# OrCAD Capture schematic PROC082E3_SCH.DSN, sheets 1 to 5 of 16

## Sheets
1 01. TABLE OF CONTENTS: title: TABLE OF CONTENTS; rev: E3; note: PROC082_SCH
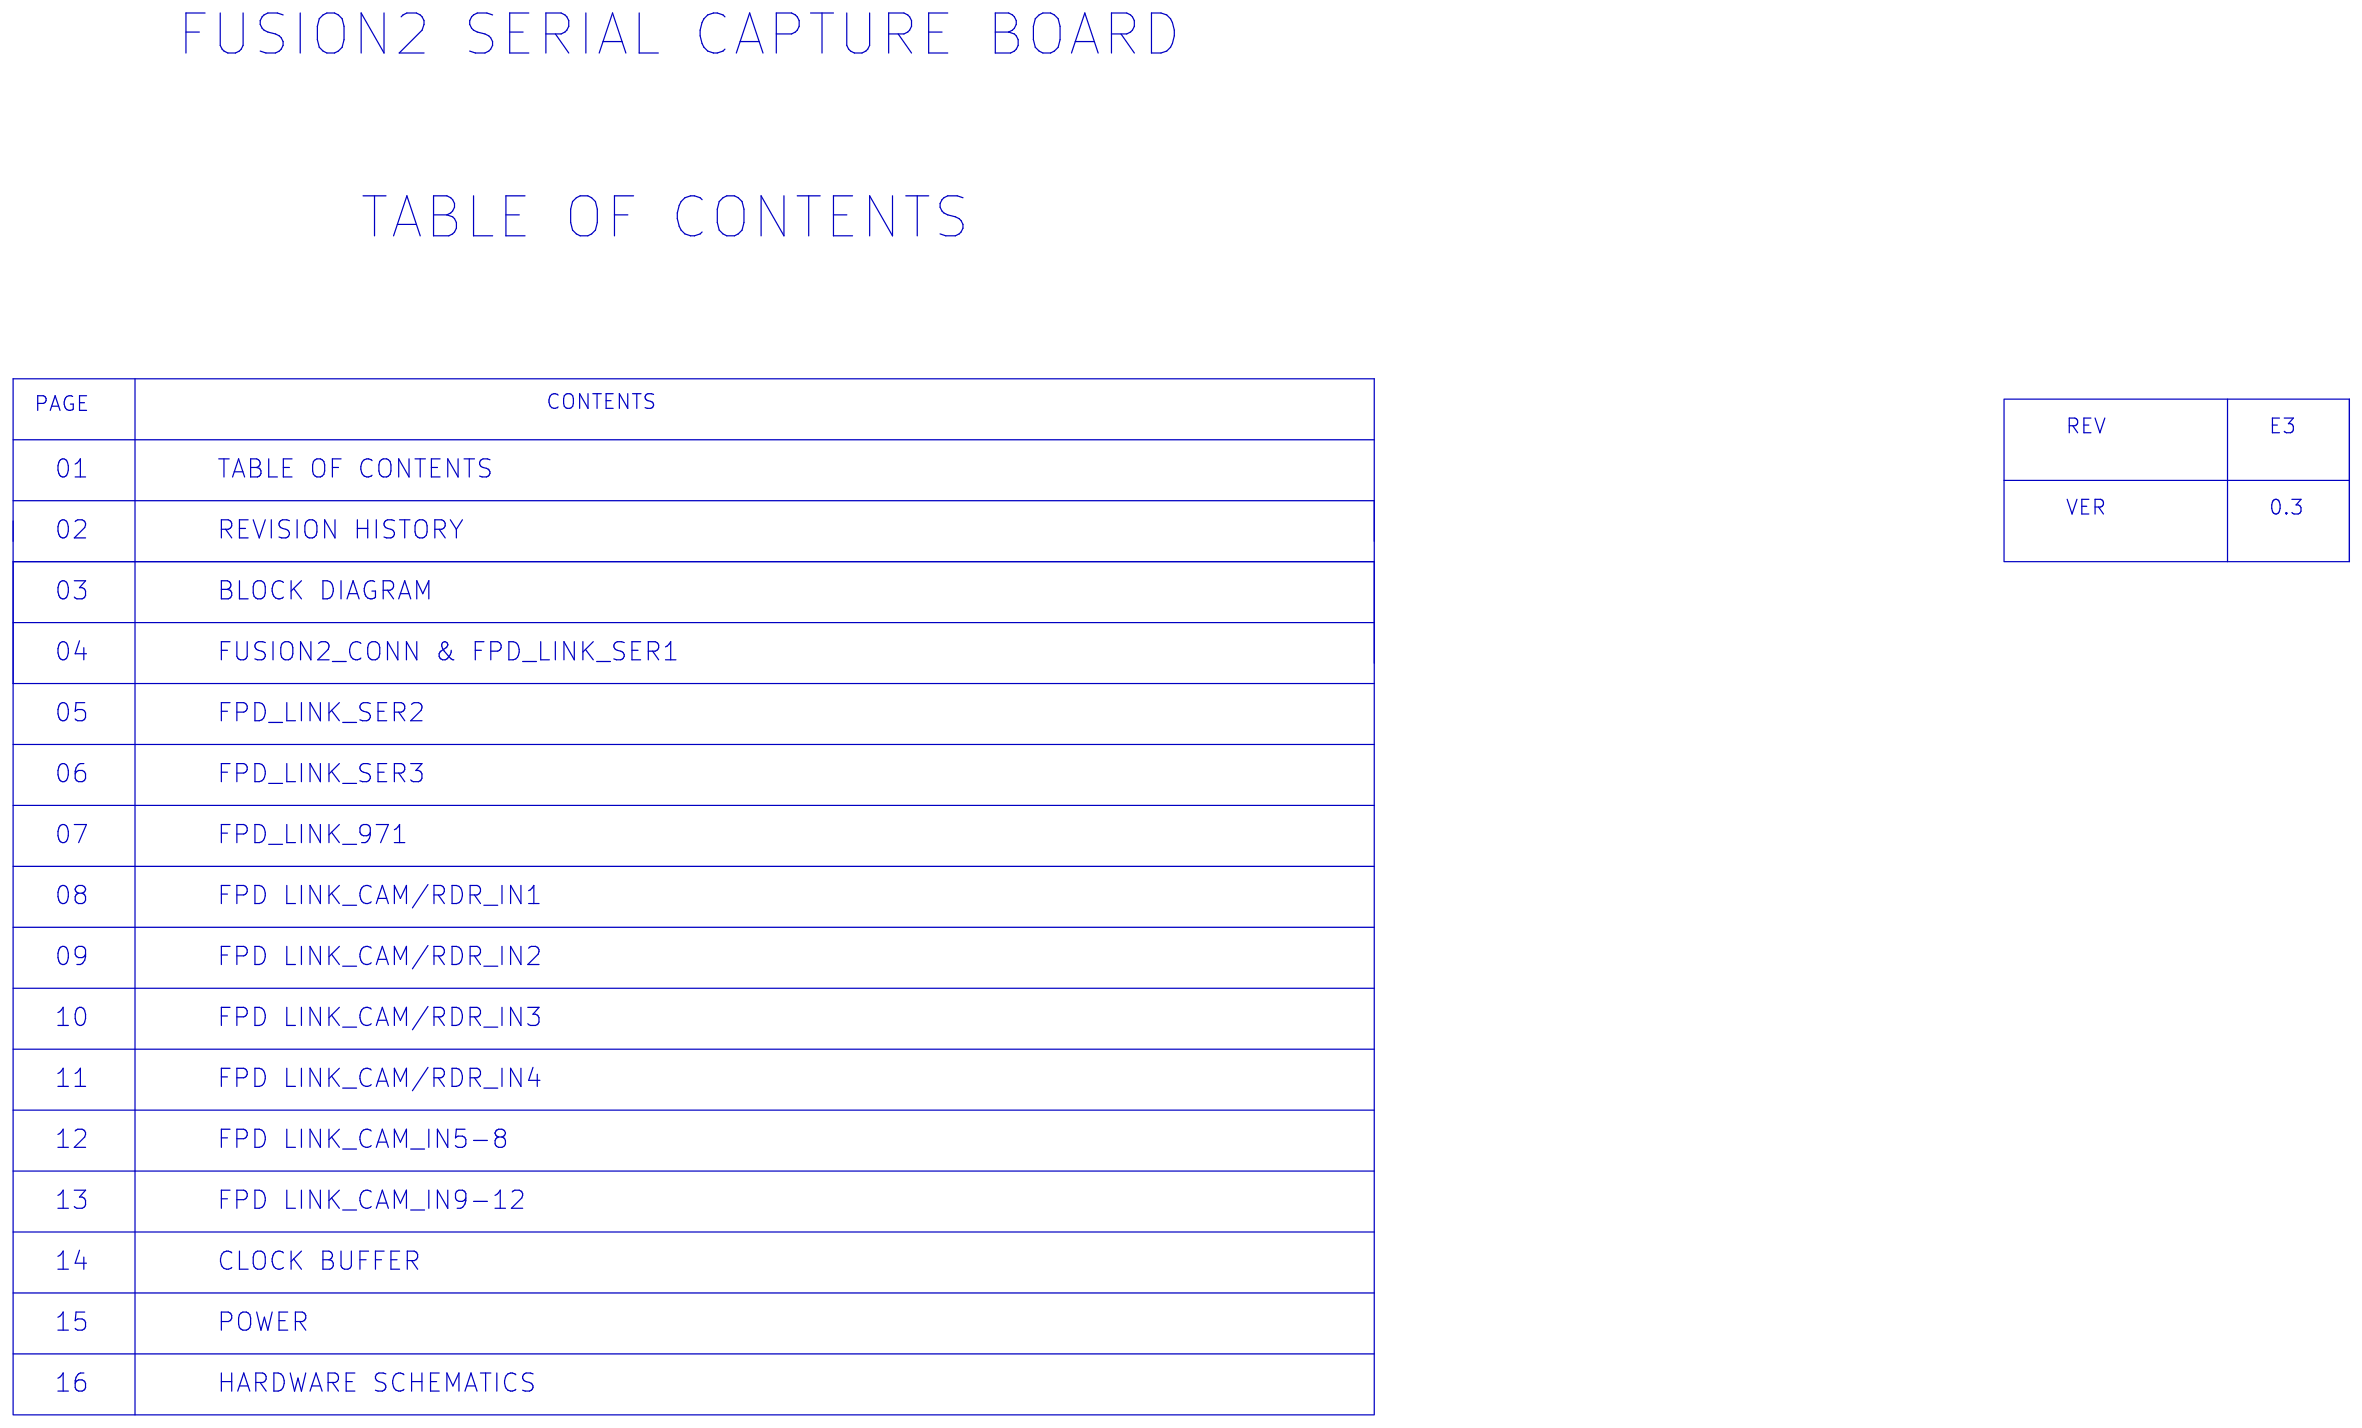
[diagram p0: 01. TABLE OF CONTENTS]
2 02. REVISION HISTORY: title: REVISION HISTORY
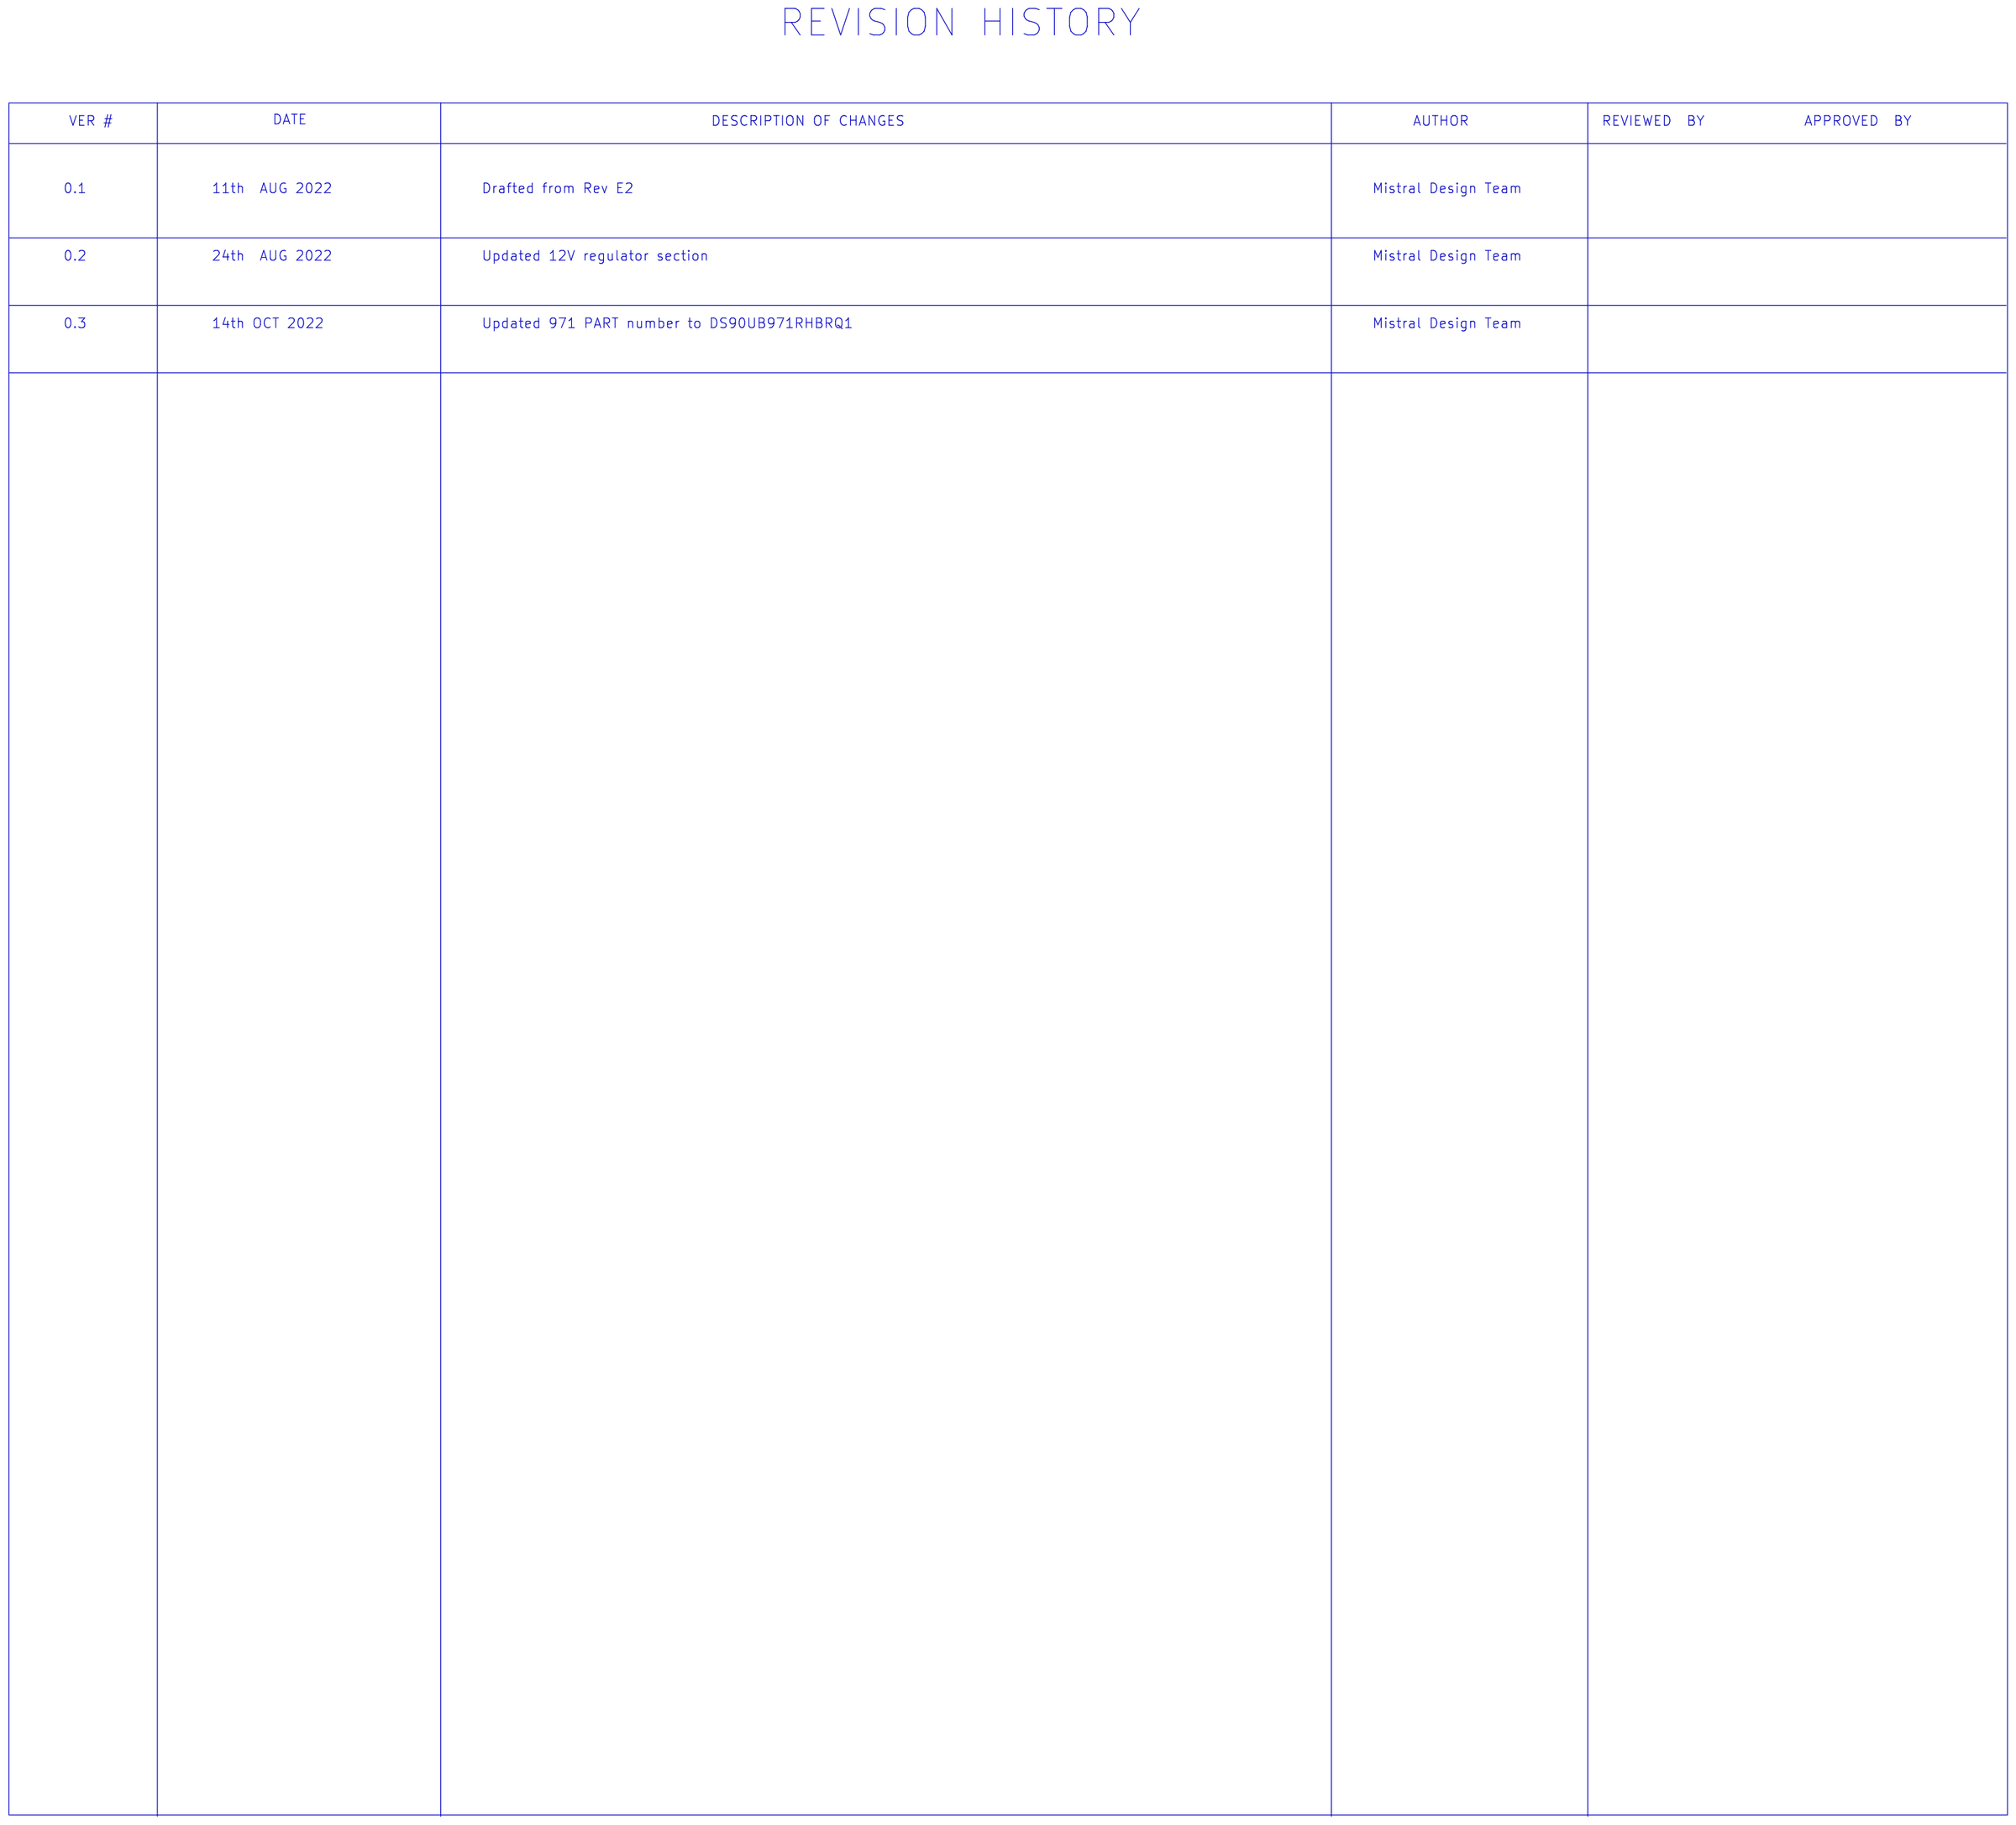
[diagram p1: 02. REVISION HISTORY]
3 03. BLOCK_DIAGRAM: title: BLOCK DIAGRAM
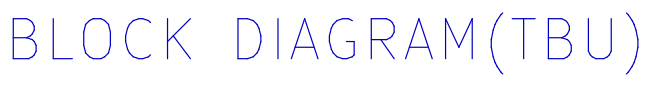
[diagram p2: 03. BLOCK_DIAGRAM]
4 04. FUSION2_CON & FPD_LINK_SER1: size C; title: FUSION2_CONN & FPD_LINK_SER1
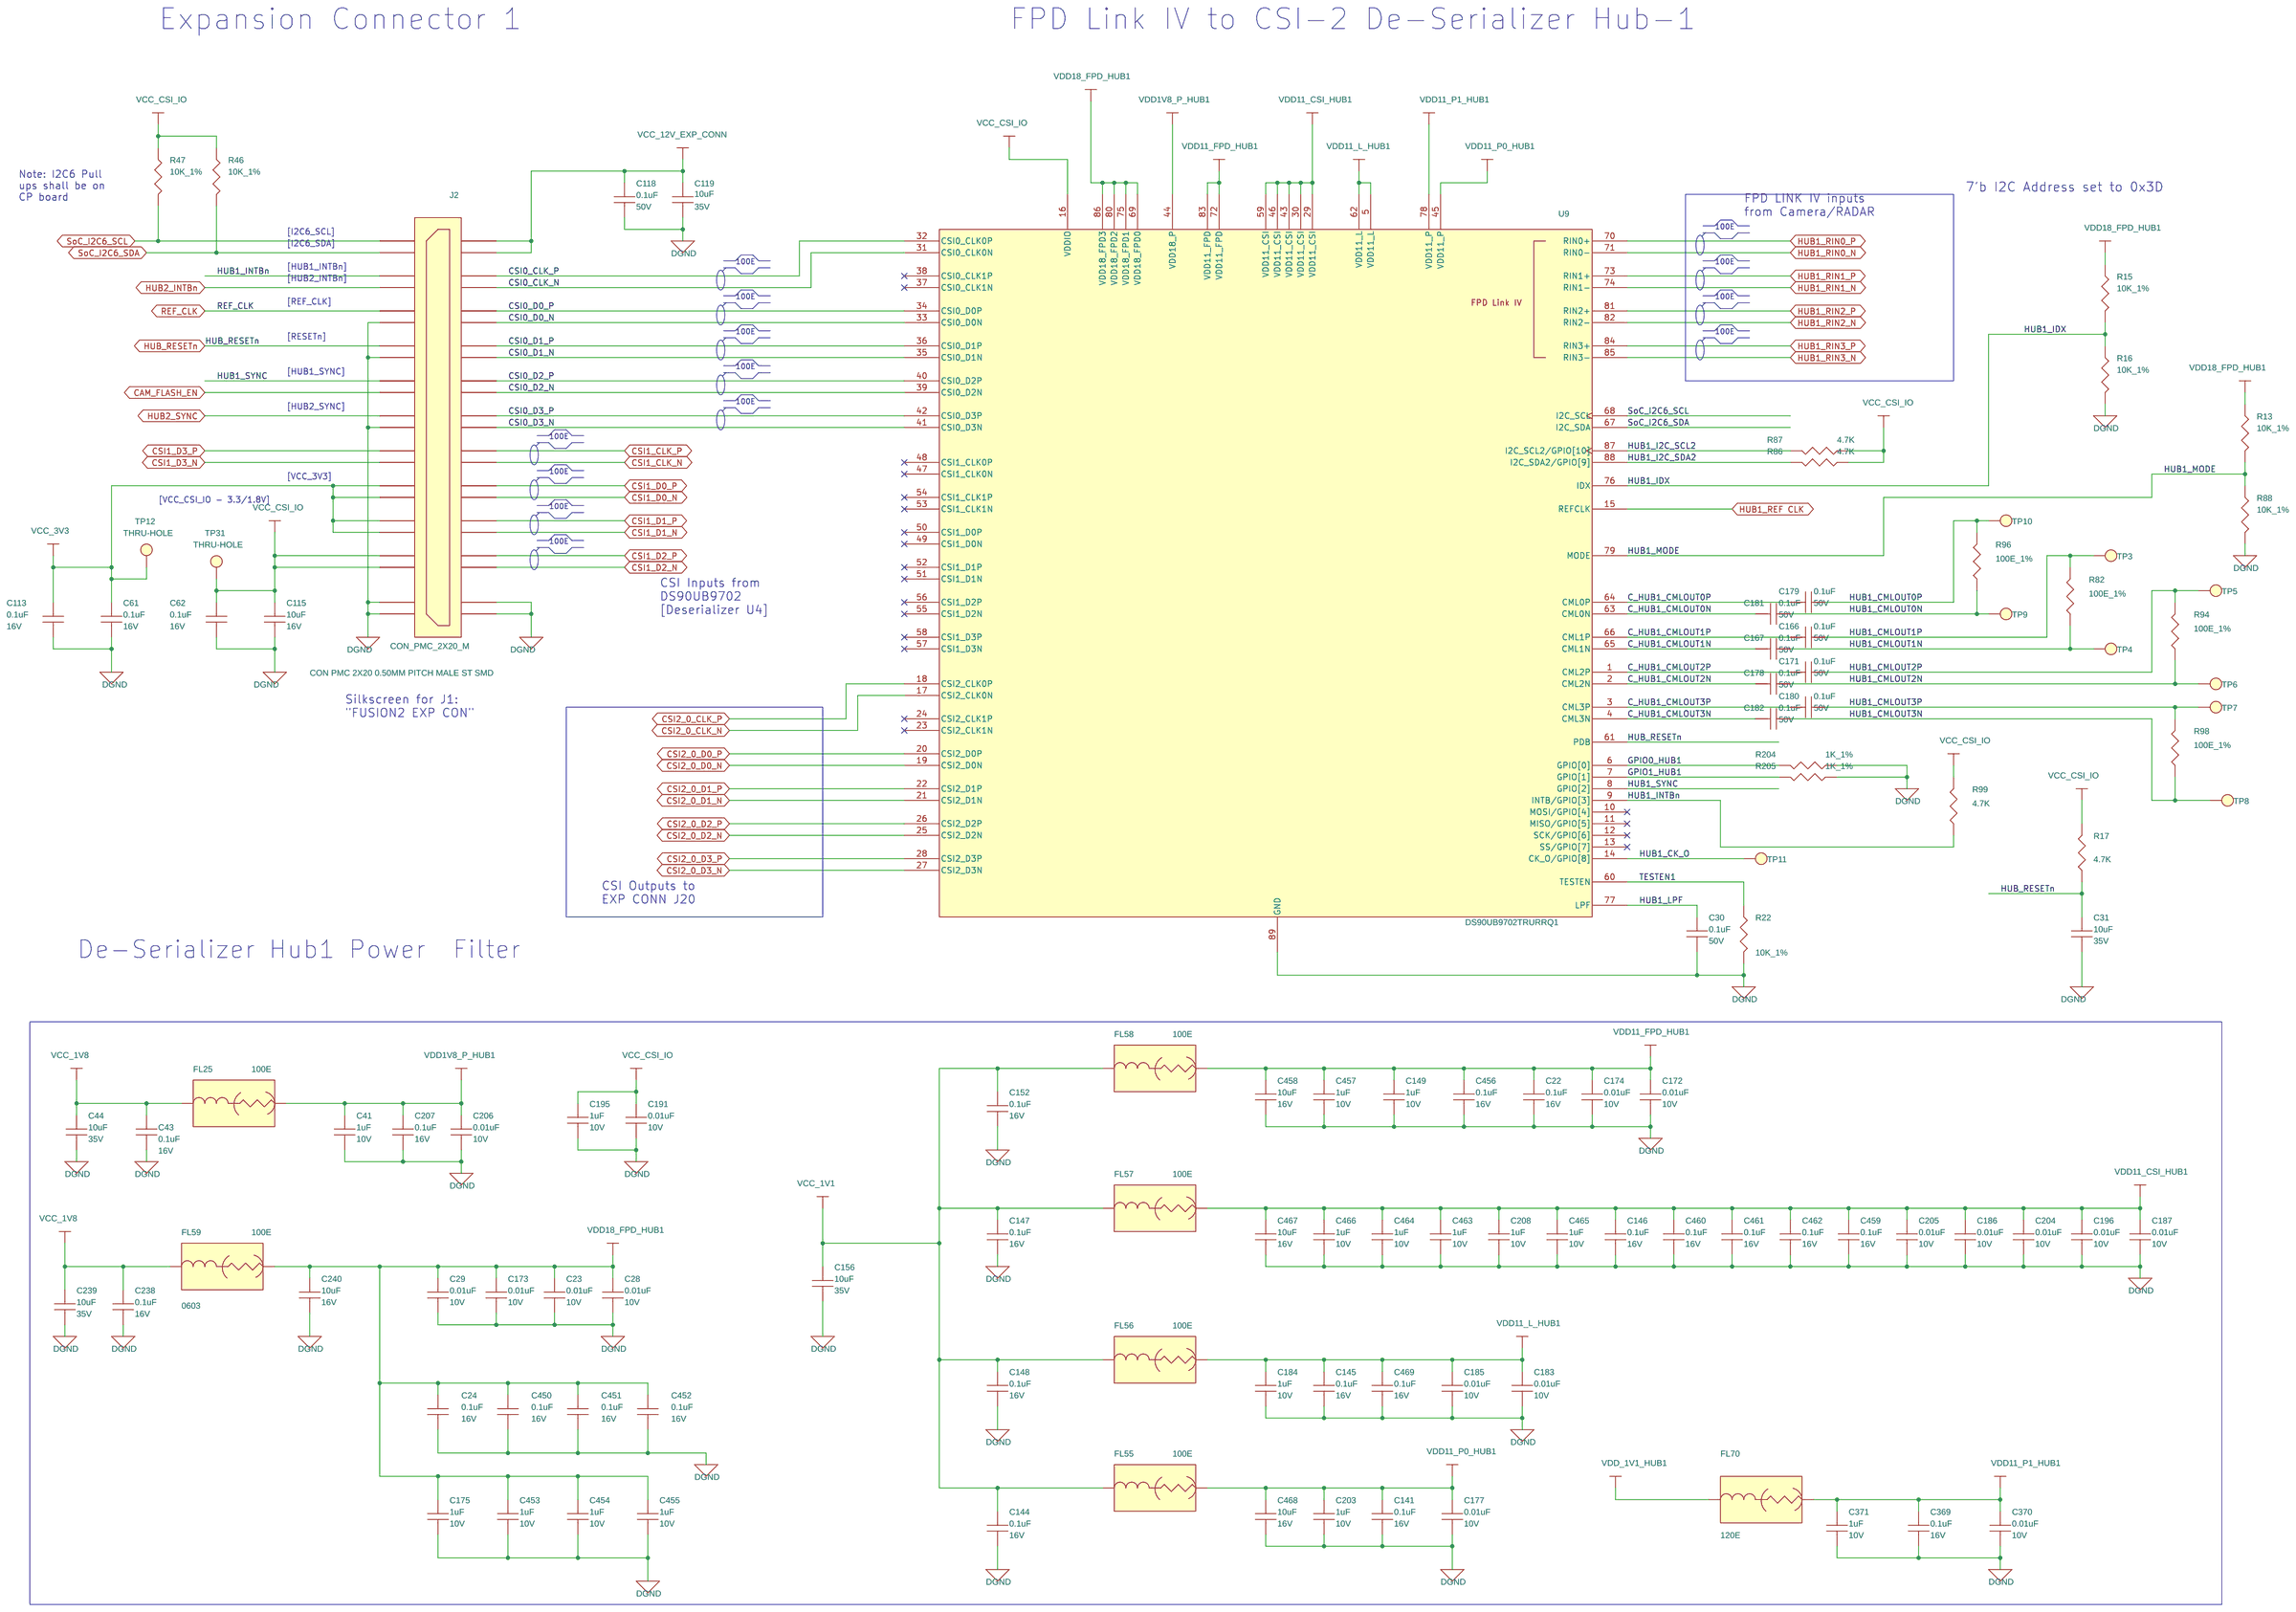
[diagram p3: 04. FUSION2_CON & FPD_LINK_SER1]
5 05. FPD_LINK_SER2: size C; title: FPD_LINK_SER2
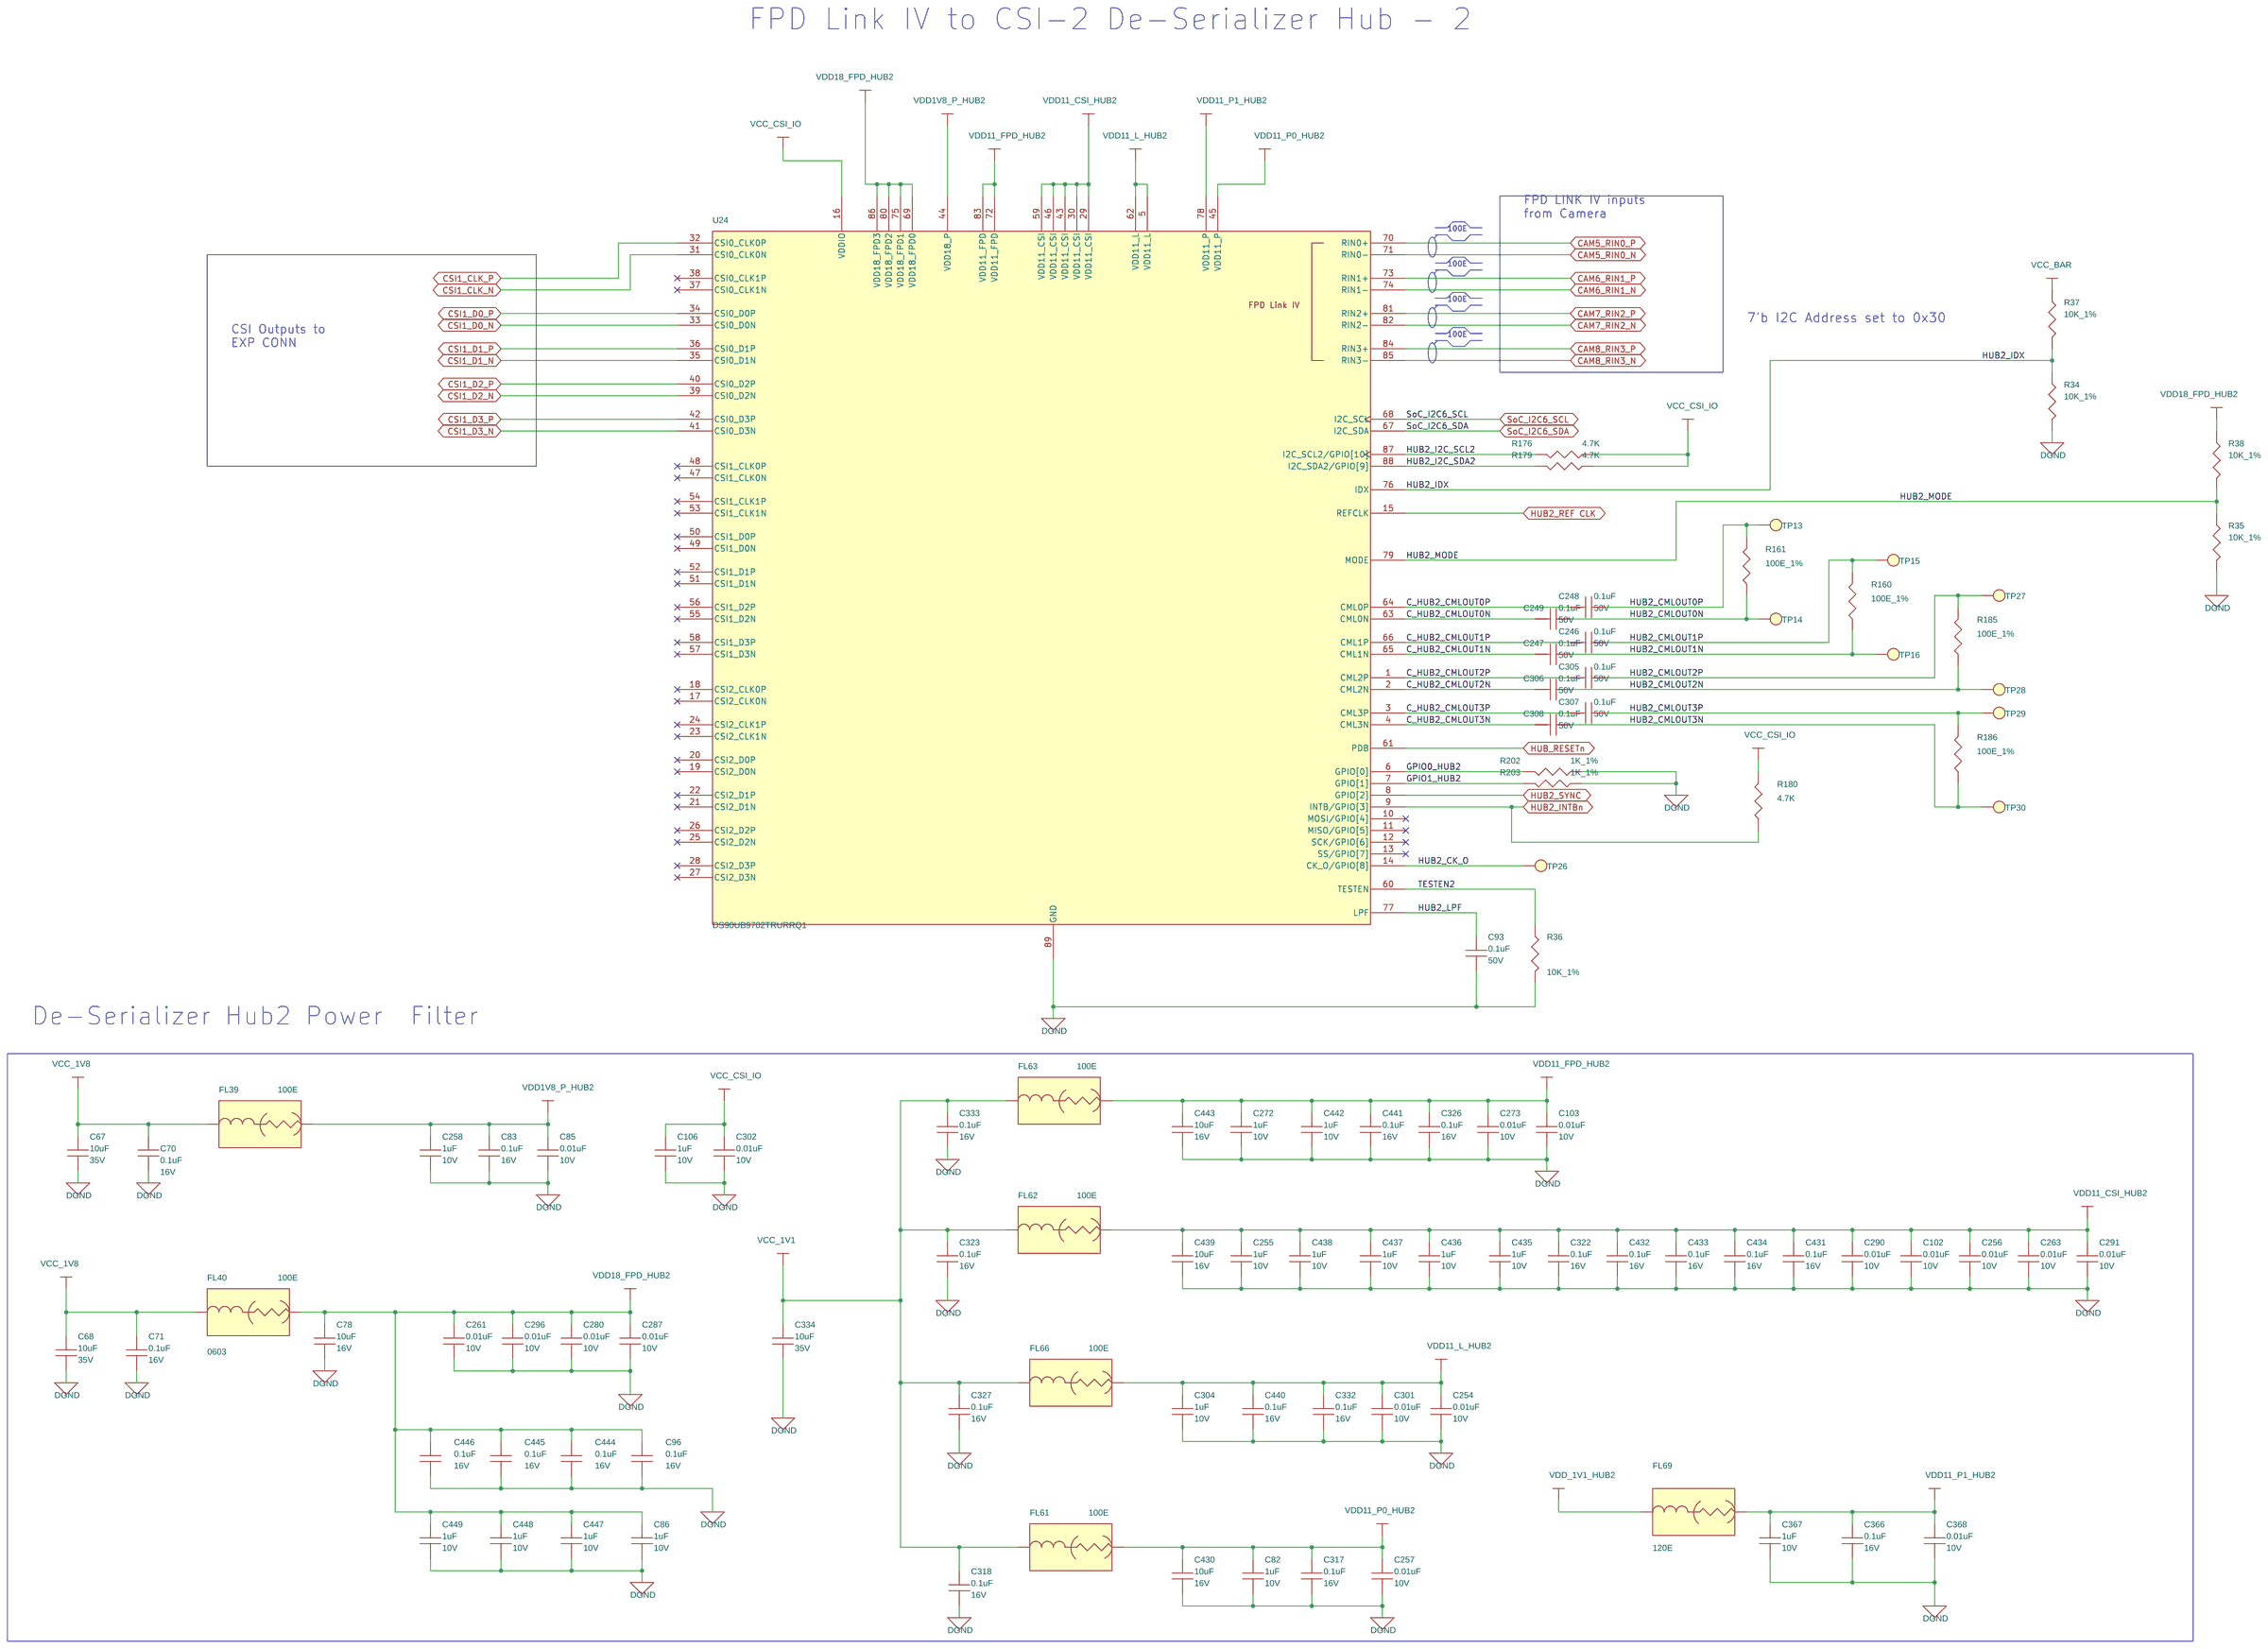
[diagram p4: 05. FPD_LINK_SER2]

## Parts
sheet 04. FUSION2_CON & FPD_LINK_SER1
C22  0.1uF  [CAP0402_0-75]
C23  0.01uF  [CAP0201_0-5]
C24  0.1uF  [CAP0402_0-75]
C28  0.01uF  [CAP0201_0-5]
C29  0.01uF  [CAP0201_0-5]
C30  0.1uF  [CAP0402_0-75]
C31  10uF  [CAP1206_1]
C41  1uF  [CAP0402_0-75]
C43  0.1uF  [CAP0402_0-75]
C44  10uF  [CAP1206_1]
C61  0.1uF  [CAP0402_0-75]
C62  0.1uF  [CAP0402_0-75]
C113  0.1uF  [CAP0402_0-75]
C115  10uF  [CAP0603_1]
C118  0.1uF  [CAP0402_0-75]
C119  10uF  [CAP1206_1]
C141  0.1uF  [CAP0402_0-75]
C144  0.1uF  [CAP0402_0-75]
C145  0.1uF  [CAP0402_0-75]
C146  0.1uF  [CAP0402_0-75]
C147  0.1uF  [CAP0402_0-75]
C148  0.1uF  [CAP0402_0-75]
C149  1uF  [CAP0402_0-75]
C152  0.1uF  [CAP0402_0-75]
C156  10uF  [CAP1206_1]
C166  0.1uF  [CAP0402_0-75]
C167  0.1uF  [CAP0402_0-75]
C171  0.1uF  [CAP0402_0-75]
C172  0.01uF  [CAP0201_0-5]
C173  0.01uF  [CAP0201_0-5]
C174  0.01uF  [CAP0201_0-5]
C175  1uF  [CAP0402_0-75]
C177  0.01uF  [CAP0201_0-5]
C178  0.1uF  [CAP0402_0-75]
C179  0.1uF  [CAP0402_0-75]
C180  0.1uF  [CAP0402_0-75]
C181  0.1uF  [CAP0402_0-75]
C182  0.1uF  [CAP0402_0-75]
C183  0.01uF  [CAP0201_0-5]
C184  1uF  [CAP0402_0-75]
C185  0.01uF  [CAP0201_0-5]
C186  0.01uF  [CAP0201_0-5]
C187  0.01uF  [CAP0201_0-5]
C191  0.01uF  [CAP0201_0-5]
C195  1uF  [CAP0402_0-75]
C196  0.01uF  [CAP0201_0-5]
C203  1uF  [CAP0402_0-75]
C204  0.01uF  [CAP0201_0-5]
C205  0.01uF  [CAP0201_0-5]
C206  0.01uF  [CAP0201_0-5]
C207  0.1uF  [CAP0402_0-75]
C208  1uF  [CAP0402_0-75]
C238  0.1uF  [CAP0402_0-75]
C239  10uF  [CAP1206_1]
C240  10uF  [CAP0603_1]
C369  0.1uF  [CAP0402_0-75]
C370  0.01uF  [CAP0201_0-5]
C371  1uF  [CAP0402_0-75]
C450  0.1uF  [CAP0402_0-75]
C451  0.1uF  [CAP0402_0-75]
C452  0.1uF  [CAP0402_0-75]
C453  1uF  [CAP0402_0-75]
C454  1uF  [CAP0402_0-75]
C455  1uF  [CAP0402_0-75]
C456  0.1uF  [CAP0402_0-75]
C457  1uF  [CAP0402_0-75]
C458  10uF  [CAP0603_1]
C459  0.1uF  [CAP0402_0-75]
C460  0.1uF  [CAP0402_0-75]
C461  0.1uF  [CAP0402_0-75]
C462  0.1uF  [CAP0402_0-75]
C463  1uF  [CAP0402_0-75]
C464  1uF  [CAP0402_0-75]
C465  1uF  [CAP0402_0-75]
C466  1uF  [CAP0402_0-75]
C467  10uF  [CAP0603_1]
C468  10uF  [CAP0603_1]
C469  0.1uF  [CAP0402_0-75]
FL25  100E  [EMIFIL_BLM18R_0603]
FL55  100E  [EMIFIL_BLM18R_0603]
FL56  100E  [EMIFIL_BLM18R_0603]
FL57  100E  [EMIFIL_BLM18R_0603]
FL58  100E  [EMIFIL_BLM18R_0603]
FL59  100E  [EMIFIL_BLM18R_0603]
FL70  120E  [EMIFIL_BLM15A_0402_0-6]
J2  CON_PMC_2X20_M  [CON_PMC2X20_QTH-020-01-D-DP-A_P_S_S_4-4]
R13  10K_1%  [RES0402_0-5]
R15  10K_1%  [RES0402_0-5]
R16  10K_1%  [RES0402_0-5]
R17  4.7K  [RES0402_0-5]
R22  10K_1%  [RES0402_0-5]
R46  10K_1%  [RES0402_0-5]
R47  10K_1%  [RES0402_0-5]
R82  100E_1%  [RES0402_0-5]
R86  4.7K  [RES0402_0-5]
R87  4.7K  [RES0402_0-5]
R88  10K_1%  [RES0402_0-5]
R94  100E_1%  [RES0402_0-5]
R96  100E_1%  [RES0402_0-5]
R98  100E_1%  [RES0402_0-5]
R99  4.7K  [RES0402_0-5]
R204  1K_1%  [RES0402_0-5]
R205  1K_1%  [RES0402_0-5]
TP3  TP40_SMD  [TP40_SMD]
TP4  TP40_SMD  [TP40_SMD]
TP5  TP40_SMD  [TP40_SMD]
TP6  TP40_SMD  [TP40_SMD]
TP7  TP40_SMD  [TP40_SMD]
TP8  TP40_SMD  [TP40_SMD]
TP9  TP40_SMD  [TP40_SMD]
TP10  TP40_SMD  [TP40_SMD]
TP11  TP40_SMD  [TP40_SMD]
TP12  THRU HOLE  [TP_40X65]
TP31  THRU HOLE  [TP_40X65]
U9  DS90UB9702TRURRQ1  [QFN88_19-68_480X480_0-9_EP6-8]
sheet 05. FPD_LINK_SER2
C67  10uF  [CAP1206_1]
C68  10uF  [CAP1206_1]
C70  0.1uF  [CAP0402_0-75]
C71  0.1uF  [CAP0402_0-75]
C78  10uF  [CAP0603_1]
C82  1uF  [CAP0402_0-75]
C83  0.1uF  [CAP0402_0-75]
C85  0.01uF  [CAP0201_0-5]
C86  1uF  [CAP0402_0-75]
C93  0.1uF  [CAP0402_0-75]
C96  0.1uF  [CAP0402_0-75]
C102  0.01uF  [CAP0201_0-5]
C103  0.01uF  [CAP0201_0-5]
C106  1uF  [CAP0402_0-75]
C246  0.1uF  [CAP0402_0-75]
C247  0.1uF  [CAP0402_0-75]
C248  0.1uF  [CAP0402_0-75]
C249  0.1uF  [CAP0402_0-75]
C254  0.01uF  [CAP0201_0-5]
C255  1uF  [CAP0402_0-75]
C256  0.01uF  [CAP0201_0-5]
C257  0.01uF  [CAP0201_0-5]
C258  1uF  [CAP0402_0-75]
C261  0.01uF  [CAP0201_0-5]
C263  0.01uF  [CAP0201_0-5]
C272  1uF  [CAP0402_0-75]
C273  0.01uF  [CAP0201_0-5]
C280  0.01uF  [CAP0201_0-5]
C287  0.01uF  [CAP0201_0-5]
C290  0.01uF  [CAP0201_0-5]
C291  0.01uF  [CAP0201_0-5]
C296  0.01uF  [CAP0201_0-5]
C301  0.01uF  [CAP0201_0-5]
C302  0.01uF  [CAP0201_0-5]
C304  1uF  [CAP0402_0-75]
C305  0.1uF  [CAP0402_0-75]
C306  0.1uF  [CAP0402_0-75]
C307  0.1uF  [CAP0402_0-75]
C308  0.1uF  [CAP0402_0-75]
C317  0.1uF  [CAP0402_0-75]
C318  0.1uF  [CAP0402_0-75]
C322  0.1uF  [CAP0402_0-75]
C323  0.1uF  [CAP0402_0-75]
C326  0.1uF  [CAP0402_0-75]
C327  0.1uF  [CAP0402_0-75]
C332  0.1uF  [CAP0402_0-75]
C333  0.1uF  [CAP0402_0-75]
C334  10uF  [CAP1206_1]
C366  0.1uF  [CAP0402_0-75]
C367  1uF  [CAP0402_0-75]
C368  0.01uF  [CAP0201_0-5]
C430  10uF  [CAP0603_1]
C431  0.1uF  [CAP0402_0-75]
C432  0.1uF  [CAP0402_0-75]
C433  0.1uF  [CAP0402_0-75]
C434  0.1uF  [CAP0402_0-75]
C435  1uF  [CAP0402_0-75]
C436  1uF  [CAP0402_0-75]
C437  1uF  [CAP0402_0-75]
C438  1uF  [CAP0402_0-75]
C439  10uF  [CAP0603_1]
C440  0.1uF  [CAP0402_0-75]
C441  0.1uF  [CAP0402_0-75]
C442  1uF  [CAP0402_0-75]
C443  10uF  [CAP0603_1]
C444  0.1uF  [CAP0402_0-75]
C445  0.1uF  [CAP0402_0-75]
C446  0.1uF  [CAP0402_0-75]
C447  1uF  [CAP0402_0-75]
C448  1uF  [CAP0402_0-75]
C449  1uF  [CAP0402_0-75]
FL39  100E  [EMIFIL_BLM18R_0603]
FL40  100E  [EMIFIL_BLM18R_0603]
FL61  100E  [EMIFIL_BLM18R_0603]
FL62  100E  [EMIFIL_BLM18R_0603]
FL63  100E  [EMIFIL_BLM18R_0603]
FL66  100E  [EMIFIL_BLM18R_0603]
FL69  120E  [EMIFIL_BLM15A_0402_0-6]
R34  10K_1%  [RES0402_0-5]
R35  10K_1%  [RES0402_0-5]
R36  10K_1%  [RES0402_0-5]
R37  10K_1%  [RES0402_0-5]
R38  10K_1%  [RES0402_0-5]
R160  100E_1%  [RES0402_0-5]
R161  100E_1%  [RES0402_0-5]
R176  4.7K  [RES0402_0-5]
R179  4.7K  [RES0402_0-5]
R180  4.7K  [RES0402_0-5]
R185  100E_1%  [RES0402_0-5]
R186  100E_1%  [RES0402_0-5]
R202  1K_1%  [RES0402_0-5]
R203  1K_1%  [RES0402_0-5]
TP13  TP40_SMD  [TP40_SMD]
TP14  TP40_SMD  [TP40_SMD]
TP15  TP40_SMD  [TP40_SMD]
TP16  TP40_SMD  [TP40_SMD]
TP26  TP40_SMD  [TP40_SMD]
TP27  TP40_SMD  [TP40_SMD]
TP28  TP40_SMD  [TP40_SMD]
TP29  TP40_SMD  [TP40_SMD]
TP30  TP40_SMD  [TP40_SMD]
U24  DS90UB9702TRURRQ1  [QFN88_19-68_480X480_0-9_EP6-8]

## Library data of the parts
C22 C24 C43 C61 C62 C70 C71 C83 C96 C113 C141 C144-C148 C152 C207 C238 C317 C318 C322 C323 C326 C327 C332 C333 C366 C369 C431-C434 C440 C441 C444-C446 C450-C452 C456 C459-C462 C469 = CAP: CAP CERAMIC 0.1uF 16V 5% X7R AUTO 0402; Automotive Alternate_mfr_name: TDK; Automotive Alternate_mfr_part_number: CGA2B1X7R1C104K050BC; Chkd/date: MANIRAJA/241018; Crtd /date: ALVY/241018; Custom_Duty: 15%; Customs_HS_Code: 85322990; Direct Alternate_mfr_name: TDK; Direct Alternate_mfr_part_number: CGA2B1X7R1C104K050BC; Distributor_name: DIGIKEY; Distributor_part_number: 490-16433-1-ND; Footprint Path: Y:\MIS_DATABASE\Library\ALTIUM_TOOL\PCB_FOOTPRINTS\Altium_Footprint_Lib.PcbLib; Height: 0.55MM; Library Path: Y:\MIS_DATABASE\Library\ALTIUM_TOOL\SCHEMATICS_PARTS\MS_DISCRETE_Library.schlib; Mfr_name: MURATA; Mfr_part_number: GCM155R71C104JA55D; Mistral Part No: 120018100055-R; Package: 0402; Part_type: CAPACITORS\CERAMIC; Project: TI_J7ES_EVM_CP; RoHS: RoHS; Temperature: -55°C+125°C; Tolerance: 5%; Voltage: 16V; Wattage: NA; Weight: 6mg; Datasheet: Y:\MIS_DATABASE\DATASHEETS\CAPACITORS\GCM155R71C104JA55D.PDF
C23 C28 C29 C85 C102 C103 C172-C174 C177 C183 C185-C187 C191 C196 C204-C206 C254 C256 C257 C261 C263 C273 C280 C287 C290 C291 C296 C301 C302 C368 C370 = CAP: CAP CERAMIC 0.01uF 10V 10% X5R 0201; Chkd/date: VASANTHA/270117; Crtd /date: MAZHAR/090909; Custom_Duty: 15%; Customs_HS_Code: 85322990; Distributor_name: DIGIKEY; Distributor_part_number: 490-3166-1-ND; Footprint Path: Y:\MIS_DATABASE\Library\ALTIUM_TOOL\PCB_FOOTPRINTS\Altium_Footprint_Lib.PcbLib; Footprint Ref: CAP0402_0-75; Height: 0.33MM; Library Path: Y:\MIS_DATABASE\Library\ALTIUM_TOOL\SCHEMATICS_PARTS\MS_DISCRETE_Library.schlib; Mfr_name: MURATA; Mfr_part_number: GRM033R61A103KA01D; Mistral Part No: 120011010015-R; Package: 0201; Part_type: CAPACITORS\CERAMIC; Project: VMEFMCD; RoHS: RoHS; Temperature: -55°C+85°C; Tolerance: 10%; Voltage: 10V; Wattage: NA; Weight: 0.33mg; Datasheet: Y:\MIS_DATABASE\DATASHEETS\CAPACITORS\MURATA-GXX-SER_NOV17.PDF
C30 C93 C118 C166 C167 C171 C178-C182 C246-C249 C305-C308 = CAP: CAP CERAMIC 0.1uF 50V 10% X7R 0402; Chkd/date: MANIRAJA/131217; Crtd /date: ALVY/131217; Custom_Duty: 15%; Customs_HS_Code: 85322990; Distributor_name: DIGIKEY; Distributor_part_number: 478-10043-1-ND; Footprint Path: Y:\MIS_DATABASE\Library\ALTIUM_TOOL\PCB_FOOTPRINTS\Altium_Footprint_Lib.PcbLib; Height: 0.56MM; Library Path: Y:\MIS_DATABASE\Library\ALTIUM_TOOL\SCHEMATICS_PARTS\MS_DISCRETE_Library.schlib; Mfr_name: AVX CORPORATION; Mfr_part_number: 04025C104KAT2A; Mistral Part No: 120011100014-R; Package: 0402; Part_type: CAPACITORS\CERAMIC; Project: ASL_LIU_TYPE-II; RoHS: RoHS; Temperature: -55°C+125°C; Tolerance: 10%; Voltage: 50V; Wattage: NA; Weight: 0.65mg; Datasheet: Y:\MIS_DATABASE\DATASHEETS\CAPACITORS\AVX_MLC.PDF
C31 C44 C67 C68 C119 C156 C239 C334 = CAP: CAP CERAMIC 10uF 35V 10% X5R 1206; Chkd/date: MANIRAJA/130618; Crtd /date: MANIRAJA/130618; Custom_Duty: 15%; Customs_HS_Code: 85322990; Distributor_name: DIGIKEY; Distributor_part_number: 490-9964-1-ND; Footprint Path: Y:\MIS_DATABASE\Library\ALTIUM_TOOL\PCB_FOOTPRINTS\Altium_Footprint_Lib.PcbLib; Height: 0.95MM; Library Path: Y:\MIS_DATABASE\Library\ALTIUM_TOOL\SCHEMATICS_PARTS\MS_DISCRETE_Library.schlib; Mfr_name: MURATA; Mfr_part_number: GRM319R6YA106KA12D; Mistral Part No: 120018060022-R; Package: 1206; Part_type: CAPACITORS\CERAMIC; Project: MYTHIC_PCIE_DB; RoHS: RoHS; Temperature: -55°C+85°C; Tolerance: 10%; Voltage: 35V; Wattage: NA; Weight: 40mg; Datasheet: Y:\MIS_DATABASE\DATASHEETS\CAPACITORS\GRM319R6YA106KA12D.PDF
C41 C82 C86 C106 C149 C175 C184 C195 C203 C208 C255 C258 C272 C304 C367 C371 C435-C438 C442 C447-C449 C453-C455 C457 C463-C466 = CAP: CAP CERAMIC 1uF 10V 10% X7S AUTO 0402; Chkd/date: MANIRAJA/100918; Crtd /date: ALVY/100918; Custom_Duty: 15%; Customs_HS_Code: 85322990; Distributor_name: DIGIKEY; Distributor_part_number: 490-13409-1-ND; Footprint Path: Y:\MIS_DATABASE\Library\ALTIUM_TOOL\PCB_FOOTPRINTS\Altium_Footprint_Lib.PcbLib; Footprint Ref: CAP0402_0-5; Height: 0.70MM; Library Path: Y:\MIS_DATABASE\Library\ALTIUM_TOOL\SCHEMATICS_PARTS\MS_DISCRETE_Library.schlib; Mfr_name: MURATA; Mfr_part_number: GCM155C71A105KE38D; Mistral Part No: 120018090021-R; Package: 0402; Part_type: CAPACITORS\CERAMIC; Project: SMART-M_SCRIPTALK_PB; RoHS: RoHS; Temperature: -55°C+125°C; Tolerance: 10%; Voltage: 10V; Wattage: NA; Weight: 6mg; Datasheet: Y:\MIS_DATABASE\DATASHEETS\CAPACITORS\MURATA-GCM-SER.PDF
C78 C115 C240 C430 C439 C443 C458 C467 C468 = CAP: CAP CERAMIC 10uF 16V 20% X6S 0603; Chkd/date: VASANTHA/170117; Crtd /date: VASANTHA/170117; Custom_Duty: 15%; Customs_HS_Code: 85322990; Distributor_name: DIGIKEY; Distributor_part_number: 490-7198-1-ND; Footprint Path: Y:\MIS_DATABASE\Library\ALTIUM_TOOL\PCB_FOOTPRINTS\Altium_Footprint_Lib.PcbLib; Height: 0.90MM; Library Path: Y:\MIS_DATABASE\Library\ALTIUM_TOOL\SCHEMATICS_PARTS\MS_DISCRETE_Library.schlib; Mfr_name: MURATA; Mfr_part_number: GRM188C81C106MA73D; Mistral Part No: 120017010004-R; Package: 0603; Part_type: CAPACITORS\CERAMIC; Project: TRMM_SMART-M_PS; RoHS: RoHS; Temperature: -55°C+105°C; Tolerance: 20%; Voltage: 16V; Wattage: NA; Weight: 6.3mg; Datasheet: Y:\MIS_DATABASE\DATASHEETS\CAPACITORS\MURATA-GXX-SER_NOV17.PDF
FL25 FL39 FL40 FL55-FL59 FL61-FL63 FL66 = EMIFILTER_IND: PASSIVE FILTER EMI 100E 2A 0603; Chkd/date: BAVISH/170811; Crtd /date: CHAITHANYA/170811; Custom_Duty: 24%; Customs_HS_Code: 85437099; Distributor_name: DIGIKEY; Distributor_part_number: BLM18EG101TN1D-ND; Footprint Path: Y:\MIS_DATABASE\Library\ALTIUM_TOOL\PCB_FOOTPRINTS\Altium_Footprint_Lib.PcbLib; Height: 0.65MM; Library Path: Y:\MIS_DATABASE\Library\ALTIUM_TOOL\SCHEMATICS_PARTS\MS_FILTER_Library.schlib; Mfr_name: MURATA; Mfr_part_number: BLM18EG101TN1D; Mistral Part No: 130011080028-R; Package: 0603; Part_type: FILTER; Project: CPCI3GADC_CARD; RoHS: RoHS; Temperature: -55°C+125°C; Tolerance: NA; Voltage: NA; Wattage: NA; Weight: NA; Datasheet: Y:\MIS_DATABASE\DATASHEETS\DISCRETES\INDUCTORS\BLM18E.PDF
FL69 FL70 = EMIFILTER_IND: IND FERRITE BEAD CHIP 120E 1.3A 0402; Chkd/date: VASANTHA/010117; Crtd /date: CHAITHANYA/150312; Custom_Duty: 24%; Customs_HS_Code: 85437099; Distributor_name: DIGIKEY; Distributor_part_number: 490-5203-1-ND; Footprint Path: Y:\MIS_DATABASE\Library\ALTIUM_TOOL\PCB_FOOTPRINTS\Altium_Footprint_Lib.PcbLib; Height: 0.55MM; Library Path: Y:\MIS_DATABASE\Library\ALTIUM_TOOL\SCHEMATICS_PARTS\MS_FILTER_Library.schlib; Mfr_name: MURATA; Mfr_part_number: BLM15PD121SN1D; Mistral Part No: 130012030043-R; Package: 0402; Part_type: FILTER; Project: GEN_3-8; RoHS: RoHS; Temperature: -55°C+125°C; Tolerance: 25%; Voltage: NA; Wattage: NA; Weight: 0.65mg; Datasheet: Y:\MIS_DATABASE\DATASHEETS\DISCRETES\INDUCTORS\BLM15X-SER.PDF
J2 = CON_20X2_QTH-020-DP: CON PMC 2X20 0.50MM PITCH MALE ST SMD; Chkd/date: MANIRAJA/251018; Crtd /date: ALVY/251018; Custom_Duty: 24%; Customs_HS_Code: 85369090; Distributor_name: DIGIKEY; Distributor_part_number: SAM10667-ND; Footprint Path: Y:\MIS_DATABASE\Library\ALTIUM_TOOL\PCB_FOOTPRINTS\Altium_Footprint_Lib.PcbLib; Height: 4.35MM; Library Path: Y:\MIS_DATABASE\Library\ALTIUM_TOOL\SCHEMATICS_PARTS\MS_CONNECTOR_Library.schlib; Mfr_name: SAMTEC; Mfr_part_number: QTH-020-01-L-D-DP-A-K; Mistral Part No: 150018100046-R; Package: SMD; Part_type: CONNECTOR\PMC; Project: TI_J7ES_EVM_CP; RoHS: RoHS; Temperature: -55°C+125°C; Tolerance: NA; Voltage: NA; Wattage: NA; Weight: NA; Datasheet: Y:\MIS_DATABASE\DATASHEETS\CONNECTORS\SAM-QTH-DP.PDF
R13 R15 R16 R22 R34-R38 R46 R47 R88 = RESISTOR: RES 10K 1/16W 1% 0402; Chkd/date: VASANTHA/201216; Crtd /date: GEETHA/290506; Custom_Duty: 15%; Customs_HS_Code: 85332119; Distributor_name: DIGIKEY; Distributor_part_number: 311-10.0KLRTR-ND; Footprint Path: Y:\MIS_DATABASE\Library\ALTIUM_TOOL\PCB_FOOTPRINTS\Altium_Footprint_Lib.PcbLib; Height: 0.40MM; Library Path: Y:\MIS_DATABASE\Library\ALTIUM_TOOL\SCHEMATICS_PARTS\MS_DISCRETE_Library.schlib; Mfr_name: YAGEO AMERICA; Mfr_part_number: RC0402FR-0710KL; Mistral Part No: 110015090015-R; Package: 0402; Part_type: RESISTORS\FIXED; Project: VOCERA; RoHS: RoHS; Temperature: -55°C+155°C; Tolerance: 1%; Voltage: NA; Wattage: 1/16W; Weight: 0.65mg; Datasheet: Y:\MIS_DATABASE\DATASHEETS\RESISTORS\RCXXXXL-SER_MAR18.PDF
R17 R86 R87 R99 R176 R179 R180 = RESISTOR: RES 4.7K 1/16W 5% 0402; Chkd/date: VASANTHA/281216; Crtd /date: BAVISH/010611; Custom_Duty: 15%; Customs_HS_Code: 85332119; Distributor_name: DIGIKEY; Distributor_part_number: 541-4.7KJCT-ND; Footprint Path: Y:\MIS_DATABASE\Library\ALTIUM_TOOL\PCB_FOOTPRINTS\Altium_Footprint_Lib.PcbLib; Height: 0.40MM; Library Path: Y:\MIS_DATABASE\Library\ALTIUM_TOOL\SCHEMATICS_PARTS\MS_DISCRETE_Library.schlib; Mfr_name: VISHAY; Mfr_part_number: CRCW04024K70JNED; Mistral Part No: 110011060001-R; Package: 0402; Part_type: RESISTORS\FIXED; Project: AM4515_EVM_LCD; RoHS: RoHS; Temperature: -55°C+155°C; Tolerance: 5%; Voltage: NA; Wattage: 1/16W; Weight: 0.65mg; Datasheet: Y:\MIS_DATABASE\DATASHEETS\RESISTORS\CRCW0603.PDF
R82 R94 R96 R98 R160 R161 R185 R186 = RESISTOR: RES 100E 1/10W 1% 0402; Chkd/date: MANIRAJA/130617; Crtd /date: JEBRAN/040715; Custom_Duty: 15%; Customs_HS_Code: 85332119; Distributor_name: DIGIKEY; Distributor_part_number: P100LCT-ND; Footprint Path: Y:\MIS_DATABASE\Library\ALTIUM_TOOL\PCB_FOOTPRINTS\Altium_Footprint_Lib.PcbLib; Height: 0.40MM; Library Path: Y:\MIS_DATABASE\Library\ALTIUM_TOOL\SCHEMATICS_PARTS\MS_DISCRETE_Library.schlib; Mfr_name: PANASONIC-ECG; Mfr_part_number: ERJ-2RKF1000X; Mistral Part No: 110018020036-R; Package: 0402; Part_type: RESISTORS\FIXED; Project: CYPHY_FVB; RoHS: RoHS; Temperature: -55°C+155°C; Tolerance: 1%; Voltage: NA; Wattage: 1/10W; Weight: 0.8mg; Datasheet: Y:\MIS_DATABASE\DATASHEETS\RESISTORS\PAN-ERJSER_NOV17.PDF
R202-R205 = RESISTOR: RES 1K 1/10W 1% 0402; Chkd/date: VASANTHA/281216; Crtd /date: MAZHAR/150506; Custom_Duty: 15%; Customs_HS_Code: 85332119; Distributor_name: DIGIKEY; Distributor_part_number: P1.00KLCT-ND; Footprint Path: Y:\MIS_DATABASE\Library\ALTIUM_TOOL\PCB_FOOTPRINTS\Altium_Footprint_Lib.PcbLib; Height: 0.40MM; Library Path: Y:\MIS_DATABASE\Library\ALTIUM_TOOL\SCHEMATICS_PARTS\MS_DISCRETE_Library.schlib; Mfr_name: PANASONIC-ECG; Mfr_part_number: ERJ-2RKF1001X; Mistral Part No: 110009030411-R; Package: 0402; Part_type: RESISTORS\FIXED; Project: VOCERA; RoHS: RoHS; Temperature: -55°C+155°C; Tolerance: 1%; Voltage: NA; Wattage: 1/10W; Weight: 0.8mg; Datasheet: Y:\MIS_DATABASE\DATASHEETS\RESISTORS\PAN-ERJSER_NOV17.PDF
TP3-TP11 TP13-TP16 TP26-TP30 = TESTPOINT: TESTPOINT CIR 40 SMD; Chkd/date: MAZHAR/190505; Crtd /date: MAZHAR/190505; Distributor_name: NA; Distributor_part_number: NA; Footprint Path: Y:\MIS_DATABASE\Library\ALTIUM_TOOL\PCB_FOOTPRINTS\Altium_Footprint_Lib.PcbLib; Height: NA; Library Path: Y:\MIS_DATABASE\Library\ALTIUM_TOOL\SCHEMATICS_PARTS\MS_DISCRETE_Library.schlib; MECHANICAL 3D STEP FILE: NA; Mfr_name: LOCAL; Mistral Part No: 130009030933; Package: SMD; Project: RAINIER-3; RoHS: NA; Temperature: NA; Tolerance: NA; Voltage: NA; Wattage: NA; Weight: NA; Datasheet: NA
TP12 TP31 = TESTPOINT: TESTPOINT 1.0MM DRILL PTH; Chkd/date: MAZHAR/271211; Crtd /date: SHREESHAIL/041005; Distributor_name: NA; Distributor_part_number: NA; Height: NA; Mfr_name: LOCAL; Mistral Part No: 130009030938; Package: THRU-HOLE; Project: HSE; Datasheet: NA
U9 U24 = DS90UB9702-Q1_VQFNP88: IC 8.4Gbps 4 FPD-LINK IV DESERIALIZER HUB WITH DUAL CSI-2 O/P PORTS FOR 8MP+ CAMERAS VQFNP88; Chkd/date: MANIRAJA/230718; Crtd /date: ALVY/200718; Custom_Duty: 15%; Customs_HS_Code: 85423100; Distributor_name: NA; Distributor_part_number: NA; Footprint Path: Y:\MIS_DATABASE\Library\ALTIUM_TOOL\PCB_FOOTPRINTS\Altium_Footprint_Lib.PcbLib; Height: 0.90MM; Library Path: Y:\MIS_DATABASE\Library\ALTIUM_TOOL\SCHEMATICS_PARTS\MS_MISCINTERFACE_Library.schlib; Mfr_name: TEXAS INSTRUMENTS; Mistral Part No: 141018070009; Package: VQFNP88; Part_type: ICS\INTERFACE; Project: TI_J7ES_EVM_FUSION2_SER_CAP; RoHS: NA; Temperature: -40°C+105°C; Tolerance: NA; Voltage: NA; Wattage: NA; Weight: NA; Datasheet: Y:\MIS_DATABASE\DATASHEETS\ICS\INTERFACE\DS90UB9702-Q1_MAR19.PDF

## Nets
DGND: C22.2 C23.2 C24.2 C28.2 C29.2 C30.2 C31.2 C41.2 C43.2 C44.2 C61.2 C62.2 C67.2 C68.2 C70.2 C71.2 C78.2 C82.2 C83.2 C85.2 C86.2 C93.2 C96.2 C102.2 C103.2 C106.2 C113.2 C115.2 C118.2 C119.2 C141.2 C144.2 C145.2 C146.2 C147.2 C148.2 C149.2 C152.2 C156.2 C172.2 C173.2 C174.2 C175.2 C177.2 C183.2 C184.2 C185.2 C186.2 C187.2 C191.2 C195.2 C196.2 C203.2 C204.2 C205.2 C206.2 C207.2 C208.2 C238.2 C239.2 C240.2 C254.2 C255.2 C256.2 C257.2 C258.2 C261.2 C263.2 C272.2 C273.2 C280.2 C287.2 C290.2 C291.2 C296.2 C301.2 C302.2 C304.2 C317.2 C318.2 C322.2 C323.2 C326.2 C327.2 C332.2 C333.2 C334.2 C366.2 C367.2 C368.2 C369.2 C370.2 C371.2 C430.2 C431.2 C432.2 C433.2 C434.2 C435.2 C436.2 C437.2 C438.2 C439.2 C440.2 C441.2 C442.2 C443.2 C444.2 C445.2 C446.2 C447.2 C448.2 C449.2 C450.2 C451.2 C452.2 C453.2 C454.2 C455.2 C456.2 C457.2 C458.2 C459.2 C460.2 C461.2 C462.2 C463.2 C464.2 C465.2 C466.2 C467.2 C468.2 C469.2 J2.12 J2.16 J2.24 J2.SH1 J2.SH2 J2.SH3 J2.SH4 R16.2 R22.2 R34.2 R35.2 R36.2 R88.2 R202.1 R203.1 R204.1 R205.1 U9.89(GND) U24.89(GND) ; also on sheet 6 7 8 9 10 11 13 14 15 16
VCC_1V1: C144.1 C147.1 C148.1 C152.1 C156.1 C318.1 C323.1 C327.1 C333.1 C334.1 FL55.1 FL56.1 FL57.1 FL58.1 FL61.1 FL62.1 FL63.1 FL66.1 ; also on sheet 6 11
VCC_1V8: C43.1 C44.1 C67.1 C68.1 C70.1 C71.1 C238.1 C239.1 FL25.1 FL39.1 FL40.1 FL59.1 ; also on sheet 6 7 10 11
VCC_3V3: C61.1 C113.1 J2.30 J2.32 J2.34 J2.36 TP12.1(TP) ; also on sheet 6 10 11
VCC_12V_EXP_CONN: C118.1 C119.1 J2.1 J2.3 ; also on sheet 6 11
VCC_CSI_IO: C62.1 C106.1 C115.1 C191.1 C195.1 C302.1 J2.38 J2.40 R17.1 R46.1 R47.1 R86.2 R87.2 R99.2 R176.2 R179.2 R180.2 TP31.1(TP) U9.16(VDDIO) U24.16(VDDIO) ; also on sheet 6 10 11
VDD1V8_P_HUB1: C41.1 C206.1 C207.1 FL25.2 U9.44(VDD18_P)
VDD1V8_P_HUB2: C83.1 C85.1 C258.1 FL39.2 U24.44(VDD18_P)
VDD11_CSI_HUB1: C146.1 C186.1 C187.1 C196.1 C204.1 C205.1 C208.1 C459.1 C460.1 C461.1 C462.1 C463.1 C464.1 C465.1 C466.1 C467.1 FL57.2 U9.29(VDD11_CSI) U9.30(VDD11_CSI) U9.43(VDD11_CSI) U9.46(VDD11_CSI) U9.59(VDD11_CSI)
VDD11_CSI_HUB2: C102.1 C255.1 C256.1 C263.1 C290.1 C291.1 C322.1 C431.1 C432.1 C433.1 C434.1 C435.1 C436.1 C437.1 C438.1 C439.1 FL62.2 U24.29(VDD11_CSI) U24.30(VDD11_CSI) U24.43(VDD11_CSI) U24.46(VDD11_CSI) U24.59(VDD11_CSI)
VDD11_FPD_HUB1: C22.1 C149.1 C172.1 C174.1 C456.1 C457.1 C458.1 FL58.2 U9.72(VDD11_FPD) U9.83(VDD11_FPD)
VDD11_FPD_HUB2: C103.1 C272.1 C273.1 C326.1 C441.1 C442.1 C443.1 FL63.2 U24.72(VDD11_FPD) U24.83(VDD11_FPD)
VDD11_L_HUB1: C145.1 C183.1 C184.1 C185.1 C469.1 FL56.2 U9.5(VDD11_L) U9.62(VDD11_L)
VDD11_L_HUB2: C254.1 C301.1 C304.1 C332.1 C440.1 FL66.2 U24.5(VDD11_L) U24.62(VDD11_L)
VDD11_P0_HUB1: C141.1 C177.1 C203.1 C468.1 FL55.2 U9.45(VDD11_P)
VDD11_P0_HUB2: C82.1 C257.1 C317.1 C430.1 FL61.2 U24.45(VDD11_P)
VDD11_P1_HUB1: C369.1 C370.1 C371.1 FL70.2 U9.78(VDD11_P)
VDD11_P1_HUB2: C366.1 C367.1 C368.1 FL69.2 U24.78(VDD11_P)
VDD18_FPD_HUB1: C23.1 C24.1 C28.1 C29.1 C173.1 C175.1 C240.1 C450.1 C451.1 C452.1 C453.1 C454.1 C455.1 FL59.2 R13.1 R15.1 U9.69(VDD18_FPD0) U9.75(VDD18_FPD1) U9.80(VDD18_FPD2) U9.86(VDD18_FPD3)
VDD18_FPD_HUB2: C78.1 C86.1 C96.1 C261.1 C280.1 C287.1 C296.1 C444.1 C445.1 C446.1 C447.1 C448.1 C449.1 FL40.2 R37.1 R38.1 U24.69(VDD18_FPD0) U24.75(VDD18_FPD1) U24.80(VDD18_FPD2) U24.86(VDD18_FPD3)
VDD_1V1_HUB1: FL70.1 ; also on sheet 11
VDD_1V1_HUB2: FL69.1 ; also on sheet 11
C_HUB1_CMLOUT0N: C181.2 U9.63(CML0N)
C_HUB1_CMLOUT0P: C179.2 U9.64(CML0P)
C_HUB1_CMLOUT1N: C167.2 U9.65(CML1N)
C_HUB1_CMLOUT1P: C166.2 U9.66(CML1P)
C_HUB1_CMLOUT2N: C178.2 U9.2(CML2N)
C_HUB1_CMLOUT2P: C171.2 U9.1(CML2P)
C_HUB1_CMLOUT3N: C182.2 U9.4(CML3N)
C_HUB1_CMLOUT3P: C180.2 U9.3(CML3P)
C_HUB2_CMLOUT0N: C249.2 U24.63(CML0N)
C_HUB2_CMLOUT0P: C248.2 U24.64(CML0P)
C_HUB2_CMLOUT1N: C247.2 U24.65(CML1N)
C_HUB2_CMLOUT1P: C246.2 U24.66(CML1P)
C_HUB2_CMLOUT2N: C306.2 U24.2(CML2N)
C_HUB2_CMLOUT2P: C305.2 U24.1(CML2P)
C_HUB2_CMLOUT3N: C308.2 U24.4(CML3N)
C_HUB2_CMLOUT3P: C307.2 U24.3(CML3P)
CAM5_RIN0_N: U24.71(RIN0-) ; also on sheet 8
CAM5_RIN0_P: U24.70(RIN0+) ; also on sheet 8
CAM6_RIN1_N: U24.74(RIN1-) ; also on sheet 8
CAM6_RIN1_P: U24.73(RIN1+) ; also on sheet 8
CAM7_RIN2_N: U24.82(RIN2-) ; also on sheet 8
CAM7_RIN2_P: U24.81(RIN2+) ; also on sheet 8
CAM8_RIN3_N: U24.85(RIN3-) ; also on sheet 8
CAM8_RIN3_P: U24.84(RIN3+) ; also on sheet 8
CAM_FLASH_EN: J2.20
CSI0_CLK_N: J2.7 U9.31(CSI0_CLK0N)
CSI0_CLK_P: J2.5 U9.32(CSI0_CLK0P)
CSI0_D0_N: J2.11 U9.33(CSI0_D0N)
CSI0_D0_P: J2.9 U9.34(CSI0_D0P)
CSI0_D1_N: J2.15 U9.35(CSI0_D1N)
CSI0_D1_P: J2.13 U9.36(CSI0_D1P)
CSI0_D2_N: J2.19 U9.39(CSI0_D2N)
CSI0_D2_P: J2.17 U9.40(CSI0_D2P)
CSI0_D3_N: J2.23 U9.41(CSI0_D3N)
CSI0_D3_P: J2.21 U9.42(CSI0_D3P)
CSI1_CLK_N: J2.27 U24.31(CSI0_CLK0N)
CSI1_CLK_P: J2.25 U24.32(CSI0_CLK0P)
CSI1_D0_N: J2.31 U24.33(CSI0_D0N)
CSI1_D0_P: J2.29 U24.34(CSI0_D0P)
CSI1_D1_N: J2.35 U24.35(CSI0_D1N)
CSI1_D1_P: J2.33 U24.36(CSI0_D1P)
CSI1_D2_N: J2.39 U24.39(CSI0_D2N)
CSI1_D2_P: J2.37 U24.40(CSI0_D2P)
CSI1_D3_N: J2.28 U24.41(CSI0_D3N)
CSI1_D3_P: J2.26 U24.42(CSI0_D3P)
CSI2_0_CLK_N: U9.17(CSI2_CLK0N) ; also on sheet 7
CSI2_0_CLK_P: U9.18(CSI2_CLK0P) ; also on sheet 7
CSI2_0_D0_N: U9.19(CSI2_D0N) ; also on sheet 7
CSI2_0_D0_P: U9.20(CSI2_D0P) ; also on sheet 7
CSI2_0_D1_N: U9.21(CSI2_D1N) ; also on sheet 7
CSI2_0_D1_P: U9.22(CSI2_D1P) ; also on sheet 7
CSI2_0_D2_N: U9.25(CSI2_D2N) ; also on sheet 7
CSI2_0_D2_P: U9.26(CSI2_D2P) ; also on sheet 7
CSI2_0_D3_N: U9.27(CSI2_D3N) ; also on sheet 7
CSI2_0_D3_P: U9.28(CSI2_D3P) ; also on sheet 7
GPIO0_HUB1: R204.2 U9.6(GPIO[0])
GPIO0_HUB2: R202.2 U24.6(GPIO[0])
GPIO1_HUB1: R205.2 U9.7(GPIO[1])
GPIO1_HUB2: R203.2 U24.7(GPIO[1])
HUB1_CK_O: TP11.1(TP) U9.14(CK_O/GPIO[8])
HUB1_CMLOUT0N: C181.1 R96.1 TP9.1(TP)
HUB1_CMLOUT0P: C179.1 R96.2 TP10.1(TP)
HUB1_CMLOUT1N: C167.1 R82.1 TP4.1(TP)
HUB1_CMLOUT1P: C166.1 R82.2 TP3.1(TP)
HUB1_CMLOUT2N: C178.1 R94.1 TP6.1(TP)
HUB1_CMLOUT2P: C171.1 R94.2 TP5.1(TP)
HUB1_CMLOUT3N: C182.1 R98.1 TP8.1(TP)
HUB1_CMLOUT3P: C180.1 R98.2 TP7.1(TP)
HUB1_I2C_SCL2: R87.1 U9.87(I2C_SCL2/GPIO[10])
HUB1_I2C_SDA2: R86.1 U9.88(I2C_SDA2/GPIO[9])
HUB1_IDX: R15.2 R16.1 U9.76(IDX)
HUB1_INTBn: J2.6 R99.1 U9.9(INTB/GPIO[3])
HUB1_LPF: C30.1 U9.77(LPF)
HUB1_MODE: R13.2 R88.1 U9.79(MODE)
HUB1_REF CLK: U9.15(REFCLK) ; also on sheet 10
HUB1_RIN0_N: U9.71(RIN0-) ; also on sheet 13
HUB1_RIN0_P: U9.70(RIN0+) ; also on sheet 13
HUB1_RIN1_N: U9.74(RIN1-) ; also on sheet 15
HUB1_RIN1_P: U9.73(RIN1+) ; also on sheet 15
HUB1_RIN2_N: U9.82(RIN2-) ; also on sheet 14
HUB1_RIN2_P: U9.81(RIN2+) ; also on sheet 14
HUB1_RIN3_N: U9.85(RIN3-) ; also on sheet 16
HUB1_RIN3_P: U9.84(RIN3+) ; also on sheet 16
HUB1_SYNC: J2.18 U9.8(GPIO[2])
HUB2_CK_O: TP26.1(TP) U24.14(CK_O/GPIO[8])
HUB2_CMLOUT0N: C249.1 R161.1 TP14.1(TP)
HUB2_CMLOUT0P: C248.1 R161.2 TP13.1(TP)
HUB2_CMLOUT1N: C247.1 R160.1 TP16.1(TP)
HUB2_CMLOUT1P: C246.1 R160.2 TP15.1(TP)
HUB2_CMLOUT2N: C306.1 R185.1 TP28.1(TP)
HUB2_CMLOUT2P: C305.1 R185.2 TP27.1(TP)
HUB2_CMLOUT3N: C308.1 R186.1 TP30.1(TP)
HUB2_CMLOUT3P: C307.1 R186.2 TP29.1(TP)
HUB2_I2C_SCL2: R176.1 U24.87(I2C_SCL2/GPIO[10])
HUB2_I2C_SDA2: R179.1 U24.88(I2C_SDA2/GPIO[9])
HUB2_IDX: R34.1 R37.2 U24.76(IDX)
HUB2_INTBn: J2.8 R180.1 U24.9(INTB/GPIO[3])
HUB2_LPF: C93.1 U24.77(LPF)
HUB2_MODE: R35.1 R38.2 U24.79(MODE)
HUB2_REF CLK: U24.15(REFCLK) ; also on sheet 10
HUB2_SYNC: J2.22 U24.8(GPIO[2])
HUB_RESETn: C31.1 J2.14 R17.2 U9.61(PDB) U24.61(PDB) ; also on sheet 6
REF_CLK: J2.10 ; also on sheet 10
SoC_I2C6_SCL: J2.2 R47.2 U9.68(I2C_SCL) U24.68(I2C_SCL) ; also on sheet 6 7 10
SoC_I2C6_SDA: J2.4 R46.2 U9.67(I2C_SDA) U24.67(I2C_SDA) ; also on sheet 6 7 10
TESTEN1: R22.1 U9.60(TESTEN)
TESTEN2: R36.1 U24.60(TESTEN)

Not connected (* = marked no-connect by the designer): U9 10(MOSI/GPIO[4])* 11(MISO/GPIO[5])* 12(SCK/GPIO[6])* 13(SS/GPIO[7])* 23(CSI2_CLK1N)* 24(CSI2_CLK1P)* 37(CSI0_CLK1N)* 38(CSI0_CLK1P)* 47(CSI1_CLK0N)* 48(CSI1_CLK0P)* 49(CSI1_D0N)* 50(CSI1_D0P)* 51(CSI1_D1N)* 52(CSI1_D1P)* 53(CSI1_CLK1N)* 54(CSI1_CLK1P)* 55(CSI1_D2N)* 56(CSI1_D2P)* 57(CSI1_D3N)* 58(CSI1_D3P)*; U24 10(MOSI/GPIO[4])* 11(MISO/GPIO[5])* 12(SCK/GPIO[6])* 13(SS/GPIO[7])* 17(CSI2_CLK0N)* 18(CSI2_CLK0P)* 19(CSI2_D0N)* 20(CSI2_D0P)* 21(CSI2_D1N)* 22(CSI2_D1P)* 23(CSI2_CLK1N)* 24(CSI2_CLK1P)* 25(CSI2_D2N)* 26(CSI2_D2P)* 27(CSI2_D3N)* 28(CSI2_D3P)* 37(CSI0_CLK1N)* 38(CSI0_CLK1P)* 47(CSI1_CLK0N)* 48(CSI1_CLK0P)* 49(CSI1_D0N)* 50(CSI1_D0P)* 51(CSI1_D1N)* 52(CSI1_D1P)* 53(CSI1_CLK1N)* 54(CSI1_CLK1P)* 55(CSI1_D2N)* 56(CSI1_D2P)* 57(CSI1_D3N)* 58(CSI1_D3P)*

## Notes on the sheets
sheet 1
- FUSION2 SERIAL CAPTURE BOARD
- TABLE OF CONTENTS
- PAGE
- CONTENTS
- REV
- E3
- 01
- TABLE OF CONTENTS
- VER
- 0.3
- 02
- REVISION HISTORY
- 03
- BLOCK DIAGRAM
- 04
- FUSION2_CONN & FPD_LINK_SER1
- 05
- FPD_LINK_SER2
- 06
- FPD_LINK_SER3
- 07
- FPD_LINK_971
- 08
- FPD LINK_CAM/RDR_IN1
- 09
- FPD LINK_CAM/RDR_IN2
- 10
- FPD LINK_CAM/RDR_IN3
- 11
- FPD LINK_CAM/RDR_IN4
- 12
- FPD LINK_CAM_IN5-8
- 13
- FPD LINK_CAM_IN9-12
- 14
- CLOCK BUFFER
- 15
- POWER
- 16
- HARDWARE SCHEMATICS
sheet 2
- REVISION HISTORY
- VER #
- DATE
- DESCRIPTION OF CHANGES
- AUTHOR
- REVIEWED  BY
- APPROVED  BY
- 0.1
- 11th  AUG 2022
- Drafted from Rev E2
- Mistral Design Team
- 0.2
- 24th  AUG 2022
- Updated 12V regulator section
- Mistral Design Team
- 0.3
- 14th OCT 2022
- Updated 971 PART number to DS90UB971RHBRQ1
- Mistral Design Team
sheet 3
- BLOCK DIAGRAM(TBU)
sheet 4
- Expansion Connector 1
- FPD Link IV to CSI-2 De-Serializer Hub-1
- Note: I2C6 Pull
  ups shall be on
  CP board
- 7'b I2C Address set to 0x3D
- FPD LINK IV inputs
  from Camera/RADAR
- [I2C6_SCL]
- 100E
- [I2C6_SDA]
- 100E
- 100E
- [HUB1_INTBn]
- [HUB2_INTBn]
- [REF_CLK]
- 100E
- 100E
- 100E
- 100E
- [RESETn]
- [HUB1_SYNC]
- 100E
- [HUB2_SYNC]
- 100E
- 100E
- [VCC_3V3]
- 100E
- [VCC_CSI_IO - 3.3/1.8V]
- 100E
- 100E
- CSI Inputs from
  DS90UB9702
  [Deserializer U4]
- Silkscreen for J1:
  "FUSION2 EXP CON"
- CSI Outputs to
  EXP CONN J20
- De-Serializer Hub1 Power  Filter
sheet 5
- FPD Link IV to CSI-2 De-Serializer Hub - 2
- FPD LINK IV inputs
  from Camera
- 100E
- 100E
- 100E
- 7'b I2C Address set to 0x30
- CSI Outputs to
  EXP CONN
- 100E
- De-Serializer Hub2 Power  Filter
